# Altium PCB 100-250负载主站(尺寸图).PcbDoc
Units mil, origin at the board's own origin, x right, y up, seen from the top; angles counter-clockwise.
Board outline 6000 x 4000 mil, 2 copper layers (Top Layer, Bottom Layer); 2 components, 35 nets, 12 pads, 0 vias.
Unrouted connection lines stored in the file: 3.
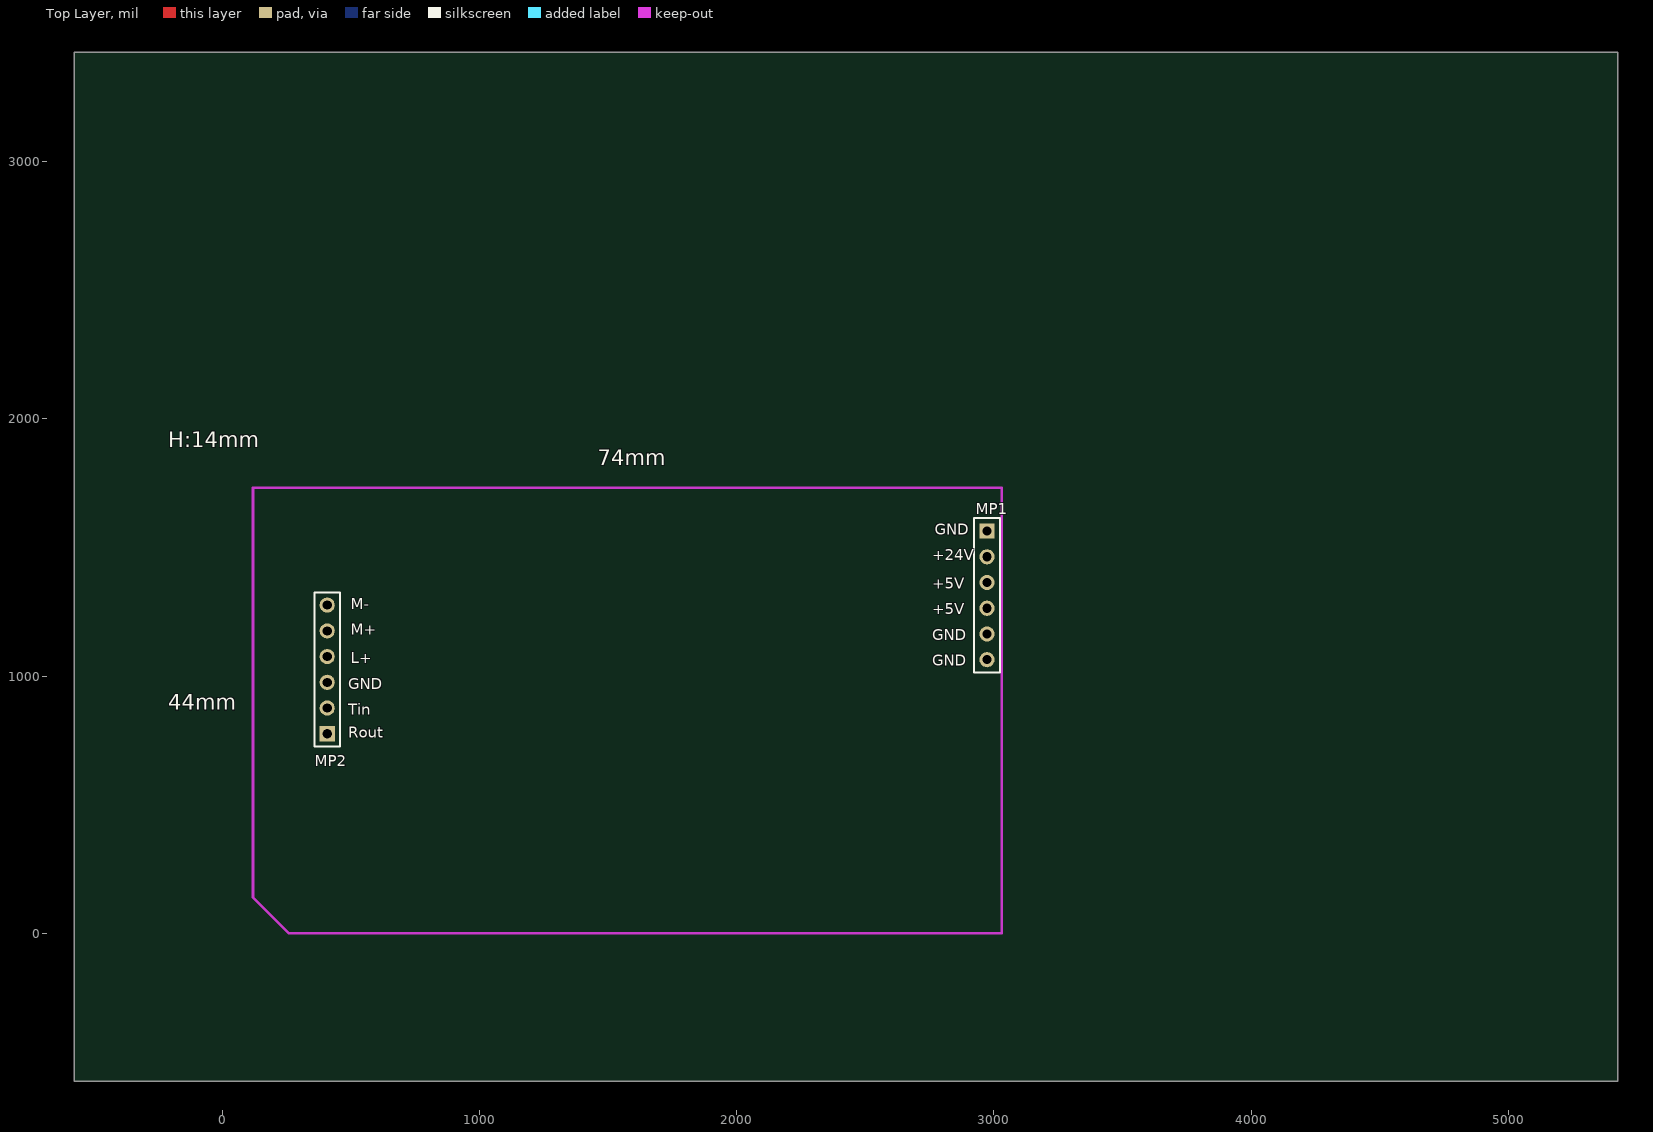
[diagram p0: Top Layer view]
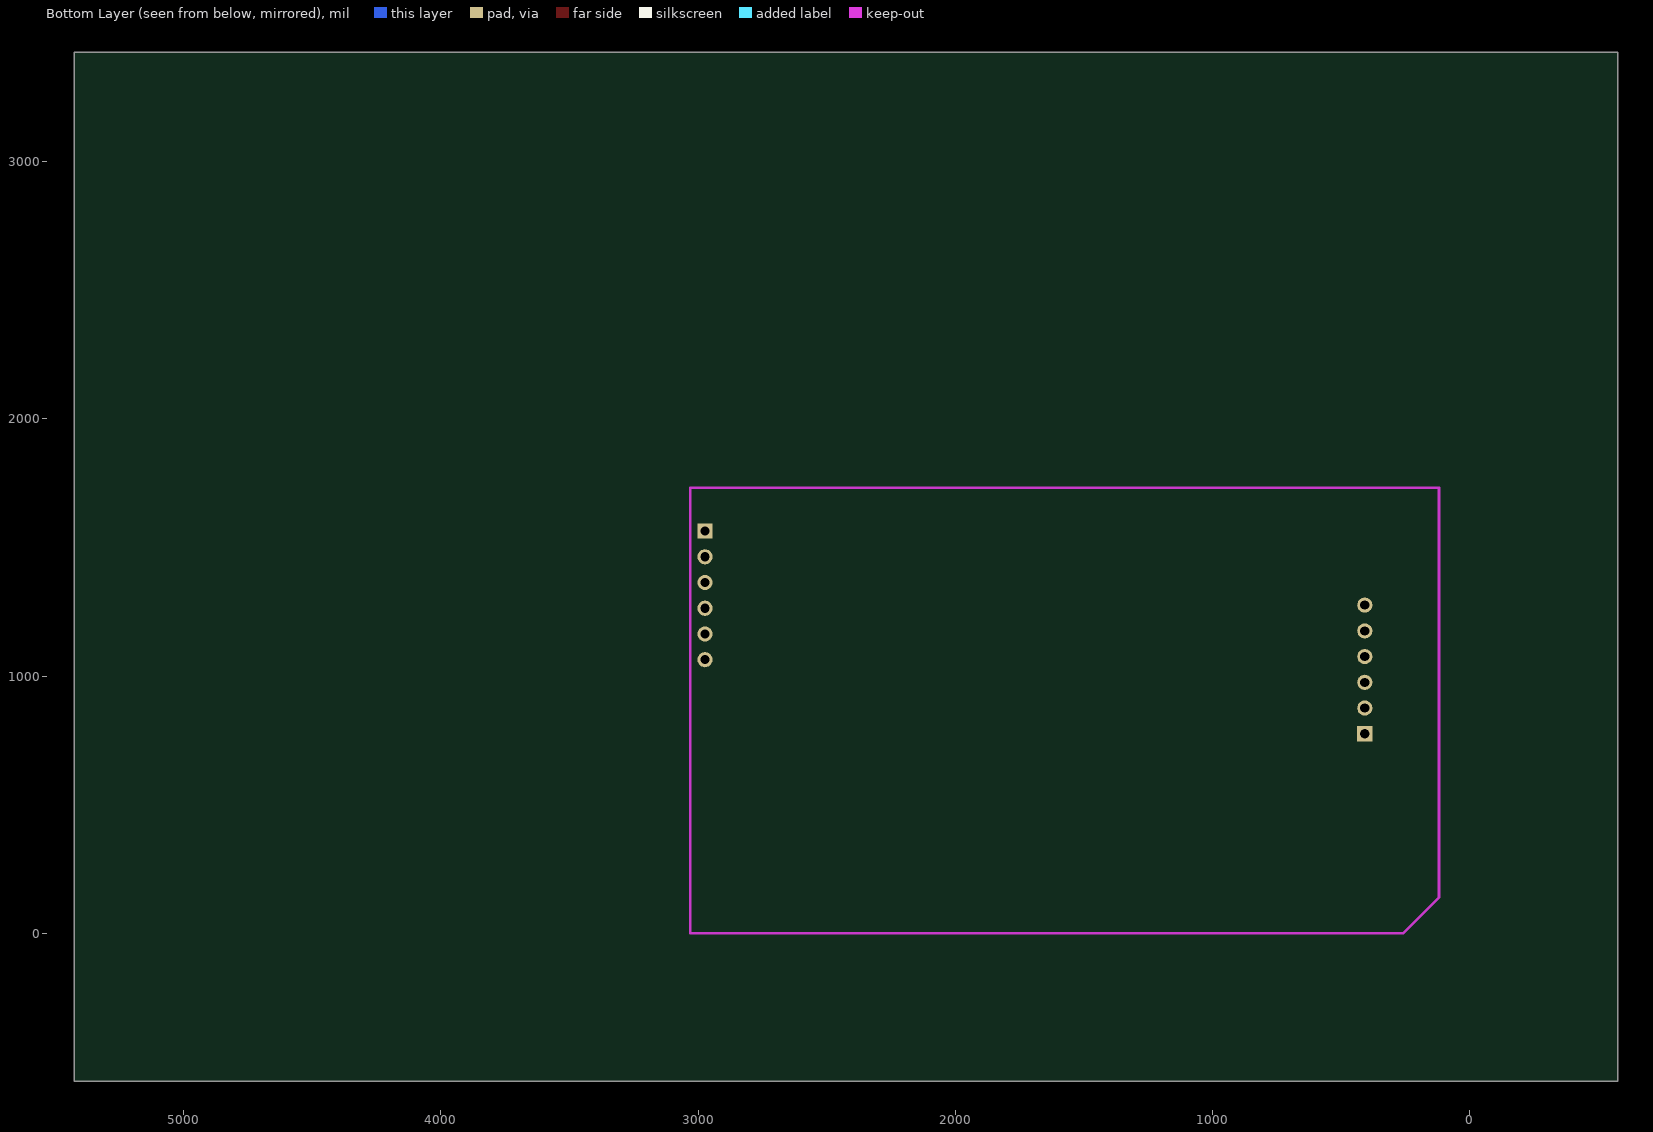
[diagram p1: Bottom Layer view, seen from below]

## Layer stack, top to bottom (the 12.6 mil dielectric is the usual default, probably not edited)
Top Layer: signal copper 1.4
Dielectric: dielectric 12.6, FR-4, Dk 4.8
Bottom Layer: signal copper 1.4

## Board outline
-574.8,-574.8 5425.2,-574.8 5425.2,3425.2 -574.8,3425.2

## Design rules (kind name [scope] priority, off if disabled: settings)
Clearance Clearance_1 [InPoly] p1: gap=25
Clearance [All] p2: gap=8
HoleSize [All] p1: absolutevalues=TRUE maxlimit=500 minlimit=0 maxpercent=80.000 minpercent=20.000
MinimumSolderMaskSliver [All] p1: minsoldermaskwidth=0
PlaneClearance [All] p1: clearance=30
PolygonConnect [All] p1: connectstyle=Direct reliefconductorwidth=10 reliefentries=4 polygonreliefangle="90 Angle"
RoomDefinition EmbeddedMBUS [InComponentClass('EmbeddedMBUS')] p1: confinementstyle=ConfineIn formatcopy=TRUE lockcomponents=FALSE outline -1084.8,-1274.8 5370,-1274.8 5370,5320 -1084.8,5320
RoutingVias [All] p1: holewidth=24 width=40 viastyle="Through Hole" minholewidth=0 minwidth=40 maxholewidth=118.11 maxwidth=275.59
SilkToSilkClearance [All] p1: silktosilkclearance=0
SilkscreenOverComponentPads [IsPad] p1: minsilkscreentomaskgap=0
SolderMaskExpansion [All] p1: expansion=4
Width [All] p1: maxlimit=50 minlimit=8 preferedwidth=10
23 further rules are at their usual default settings.

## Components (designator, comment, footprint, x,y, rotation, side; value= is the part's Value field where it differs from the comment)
MP1 "Header 6" HDR1X6 2973.35,1563.98 r270 top
MP2 "Header 6" HDR1X6 408.35,775.98 r90 top locked

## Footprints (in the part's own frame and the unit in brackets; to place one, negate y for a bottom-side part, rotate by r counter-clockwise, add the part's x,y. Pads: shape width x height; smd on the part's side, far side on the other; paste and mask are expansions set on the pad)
HDR1X6 [mm] "Connector; Header; 6 Position"
  rect 1.5x1.5 hole 0.9: 1(0,0)
  round 1.5 hole 0.9: 2(2.54,0) 3(5.08,0) 4(7.62,0) 5(10.16,0) 6(12.7,0)
  silkscreen extent -1.27,-1.27 13.97,1.27

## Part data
MP1 MP2: "Header, 6-Pin"

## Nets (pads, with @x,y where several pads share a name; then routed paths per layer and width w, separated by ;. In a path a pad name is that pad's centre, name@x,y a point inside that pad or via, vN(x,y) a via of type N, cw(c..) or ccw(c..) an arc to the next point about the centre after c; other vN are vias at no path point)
0.28V: 
36V: 
+5V: MP1.3 MP1.4
+24V: MP1.2
+36V: 
GND: MP1.1 MP1.5 MP1.6
L+: MP2.4
M+: MP2.5
M-: MP2.6
NetC2_1: 
NetC5_1: 
NetC6_1: 
NetC10_2: 
NetC15_1: 
NetD2_2: 
NetD3_1: 
NetD6_2: 
NetD7_1: 
NetL4_2: 
NetPWR_2: 
NetQ2_1: 
NetQ2_3: 
NetQ3_1: 
NetR2_1: 
NetR4_2: 
NetR5_2: 
NetR7_1: 
NetR8_1: 
NetR9_2: 
NetR10_2: 
NetR11_1: 
NetR17_2: 
NetR18_1: 
ROUT: MP2.1
RXD3: MP2.2
pads on no net: MP2.3

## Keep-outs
Keep-Out Layer:
  lines w10: 120,140 260,0 3030,0 3030,1732.28 120,1732.28 120,140

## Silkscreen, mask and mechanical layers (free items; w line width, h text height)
Top Overlay:
  text "H:14mm" at -210,1890 h60
  text "74mm" at 1460,1820 h60
  text "GND" at 2770,1550 h42
  text "+24V" at 2760,1450 h42
  text "+5V" at 2760,1340 h42
  text "M-" at 500,1260 h42
  text "+5V" at 2760,1240 h42
  text "M+" at 500,1160 h42
  text "GND" at 2760,1140 h42
  text "L+" at 500,1050 h42
  text "GND" at 2760,1040 h42
  text "GND" at 490,950 h42
  text "44mm" at -210,870 h60
  text "Tin" at 490,850 h42
  text "Rout" at 490,760 h42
